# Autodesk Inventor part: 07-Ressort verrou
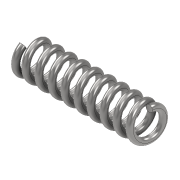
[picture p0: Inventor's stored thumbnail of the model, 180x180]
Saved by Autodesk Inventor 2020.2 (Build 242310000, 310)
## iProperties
Created: 2022-02
Part Number: 07-Ressort verrou
Material: Acier, carbone
Document SubType Name: Modeling
Designer: Philippe
Density: 7.85 g/cm^3
Appearance: Semi-poli
Project: Etau à rotule
Author: Philippe
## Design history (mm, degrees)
sketch "Esquisse1"
  geometry: L1 (0, 0)-(0, 2.554); L2 (0, 0)-(-3.203, 0); C1 r 0.3 at (-0.3, 1.3)
  constraints: 4 end point, 1 centre point, 1 horizontal, 1 tangent, 1 vertical
  dimensions: "d0" = 2 dimension on C1 L2; "d1" = 0.6 diameter of C1
feature "Hélicoïde1" sketch "Esquisse1" pitch "d2" = 1.2; turns "d4" = 1; dims "d3" = 11, "d5" = 0, angle "d6" = 90 deg, angle "d7" = 90 deg, "d8" = 90 deg, "d9" = 90 deg
node "Solide1"
